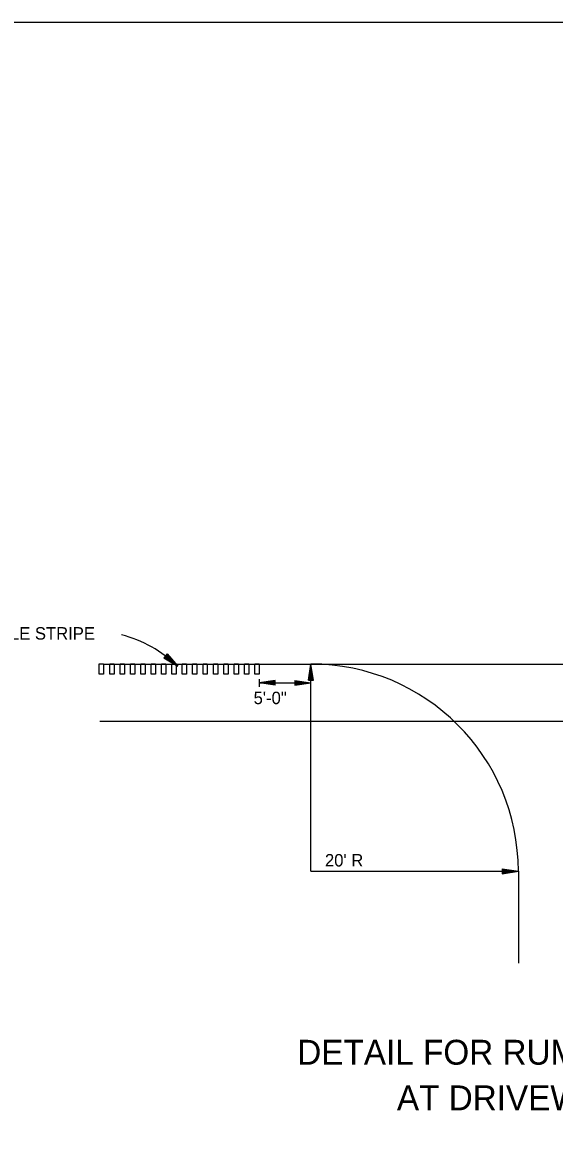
# Model space of a CAD drawing. Extents: x 1371343 to 1373043, y 378740 to 382040.
# Drawn here: x 1372437 to 1372692, y 380374 to 380915 of the extents above; entities that cross this region are included whole.
import ezdxf

# ---------------------------------------------------------------- set-up
doc = ezdxf.new("R2010")
doc.units = 0
for name, color, linetype in [('E_Existing ROW', 7, 'Continuous'), ('R_Border Notes', 7, 'Continuous'), ('R_Border PE', 7, 'Continuous')]:
    doc.layers.add(name, color=color, linetype=linetype)

msp = doc.modelspace()

# ---------------------------------------------------------------- linework, layer by layer
at = {"layer": 'E_Existing ROW'}
msp.add_lwpolyline([(1371367.92, 379865.49), (1373017.92, 379865.49), (1373017.92, 380915.49), (1371367.92, 380915.49)], close=True, dxfattribs=at)
at = {"layer": 'R_Border Notes'}
for p, q in [((1372475.93, 380607.52), (1372986.72, 380607.52)), ((1372575.6, 380508.02), (1372575.6, 380607.52)), ((1372550.73, 380600.19), (1372550.73, 380596.51)), ((1372550.73, 380598.48), (1372575.6, 380598.48)), ((1372474.28, 380580.11), (1372985.07, 380580.11)), ((1372575.6, 380508.02), (1372675.11, 380508.02)), ((1372675.11, 380508.02), (1372675.11, 380463.96))]:
    msp.add_line(p, q, dxfattribs=at)
for points in [[(1372474.03, 380602.59), (1372474.03, 380607.57), (1372476.11, 380607.57), (1372476.11, 380602.59), (1372474.03, 380602.59)], [(1372479.01, 380602.59), (1372479.01, 380607.57), (1372481.08, 380607.57), (1372481.08, 380602.59), (1372479.01, 380602.59)], [(1372483.98, 380602.59), (1372483.98, 380607.57), (1372486.06, 380607.57), (1372486.06, 380602.59), (1372483.98, 380602.59)], [(1372488.96, 380602.59), (1372488.96, 380607.57), (1372491.03, 380607.57), (1372491.03, 380602.59), (1372488.96, 380602.59)], [(1372493.93, 380602.59), (1372493.93, 380607.57), (1372496, 380607.57), (1372496, 380602.59), (1372493.93, 380602.59)], [(1372498.91, 380602.59), (1372498.91, 380607.57), (1372500.98, 380607.57), (1372500.98, 380602.59), (1372498.91, 380602.59)], [(1372503.88, 380602.59), (1372503.88, 380607.57), (1372505.95, 380607.57), (1372505.95, 380602.59), (1372503.88, 380602.59)], [(1372508.86, 380602.59), (1372508.86, 380607.57), (1372510.93, 380607.57), (1372510.93, 380602.59), (1372508.86, 380602.59)], [(1372513.83, 380602.59), (1372513.83, 380607.57), (1372515.9, 380607.57), (1372515.9, 380602.59), (1372513.83, 380602.59)], [(1372518.81, 380602.59), (1372518.81, 380607.57), (1372520.88, 380607.57), (1372520.88, 380602.59), (1372518.81, 380602.59)], [(1372523.78, 380602.59), (1372523.78, 380607.57), (1372525.85, 380607.57), (1372525.85, 380602.59), (1372523.78, 380602.59)], [(1372528.75, 380602.59), (1372528.75, 380607.57), (1372530.83, 380607.57), (1372530.83, 380602.59), (1372528.75, 380602.59)], [(1372533.73, 380602.59), (1372533.73, 380607.57), (1372535.8, 380607.57), (1372535.8, 380602.59), (1372533.73, 380602.59)], [(1372538.7, 380602.59), (1372538.7, 380607.57), (1372540.78, 380607.57), (1372540.78, 380602.59), (1372538.7, 380602.59)], [(1372543.68, 380602.59), (1372543.68, 380607.57), (1372545.75, 380607.57), (1372545.75, 380602.59), (1372543.68, 380602.59)], [(1372548.65, 380602.59), (1372548.65, 380607.57), (1372550.73, 380607.57), (1372550.73, 380602.59), (1372548.65, 380602.59)]]:
    msp.add_lwpolyline(points, dxfattribs=at)
for centre, radius, start, end in [((1372468.86, 380561.43), 62.18, 46.4613, 75.2786), ((1372575.6, 380508.02), 99.51, 0, 90)]:
    msp.add_arc(centre, radius, start, end, dxfattribs=at)
at = {"layer": 'R_Border PE'}
for p, q in [((1372506.53, 380612.35), (1372505.05, 380610.58)), ((1372505.05, 380610.58), (1372511.69, 380606.51)), ((1372505.17, 380610.73), (1372510.71, 380607.34)), ((1372505.3, 380610.88), (1372509.69, 380608.19)), ((1372505.42, 380611.03), (1372508.71, 380609.01)), ((1372505.55, 380611.18), (1372507.71, 380609.85)), ((1372505.67, 380611.33), (1372506.72, 380610.68)), ((1372505.91, 380611.6), (1372506.72, 380610.68)), ((1372506.03, 380611.75), (1372507.71, 380609.85)), ((1372506.16, 380611.91), (1372508.71, 380609.01)), ((1372506.28, 380612.05), (1372509.69, 380608.19)), ((1372506.41, 380612.2), (1372510.71, 380607.34)), ((1372506.53, 380612.35), (1372511.69, 380606.51)), ((1372574.44, 380599.82), (1372575.6, 380607.52)), ((1372574.44, 380599.82), (1372575.6, 380607.52)), ((1372574.64, 380599.82), (1372575.6, 380606.24)), ((1372574.64, 380599.82), (1372575.6, 380606.24)), ((1372574.83, 380599.82), (1372575.6, 380604.91)), ((1372574.83, 380599.82), (1372575.6, 380604.91)), ((1372575.03, 380599.82), (1372575.6, 380603.63)), ((1372575.03, 380599.82), (1372575.6, 380603.63)), ((1372576.76, 380599.82), (1372575.6, 380607.52)), ((1372576.76, 380599.82), (1372575.6, 380607.52)), ((1372576.56, 380599.82), (1372575.6, 380606.24)), ((1372576.56, 380599.82), (1372575.6, 380606.24)), ((1372576.37, 380599.82), (1372575.6, 380604.91)), ((1372576.37, 380599.82), (1372575.6, 380604.91)), ((1372576.17, 380599.82), (1372575.6, 380603.63)), ((1372576.17, 380599.82), (1372575.6, 380603.63)), ((1372558.43, 380599.64), (1372550.73, 380598.48)), ((1372558.43, 380597.33), (1372550.73, 380598.48)), ((1372558.43, 380599.45), (1372552.01, 380598.48)), ((1372558.43, 380597.52), (1372552.01, 380598.48)), ((1372558.43, 380599.25), (1372553.34, 380598.48)), ((1372558.43, 380597.72), (1372553.34, 380598.48)), ((1372558.43, 380599.06), (1372554.62, 380598.48)), ((1372558.43, 380597.91), (1372554.62, 380598.48)), ((1372558.43, 380598.86), (1372555.93, 380598.48)), ((1372558.43, 380598.11), (1372555.93, 380598.48)), ((1372558.43, 380598.66), (1372557.21, 380598.48)), ((1372558.43, 380598.3), (1372557.21, 380598.48)), ((1372558.43, 380597.33), (1372558.43, 380599.64)), ((1372567.89, 380599.64), (1372575.6, 380598.48)), ((1372567.89, 380599.64), (1372567.89, 380597.33)), ((1372567.89, 380599.45), (1372574.31, 380598.48)), ((1372567.89, 380599.25), (1372572.99, 380598.48)), ((1372567.89, 380599.06), (1372571.7, 380598.48)), ((1372567.89, 380598.86), (1372570.4, 380598.48)), ((1372567.89, 380598.66), (1372569.11, 380598.48)), ((1372567.89, 380597.33), (1372575.6, 380598.48)), ((1372567.89, 380598.11), (1372570.4, 380598.48)), ((1372567.89, 380597.72), (1372572.99, 380598.48)), ((1372567.89, 380597.52), (1372574.31, 380598.48)), ((1372567.89, 380597.91), (1372571.7, 380598.48)), ((1372567.89, 380598.3), (1372569.11, 380598.48)), ((1372574.44, 380599.82), (1372576.76, 380599.82)), ((1372574.44, 380599.82), (1372576.76, 380599.82)), ((1372575.23, 380599.82), (1372575.6, 380602.32)), ((1372575.23, 380599.82), (1372575.6, 380602.32)), ((1372575.42, 380599.82), (1372575.6, 380601.04)), ((1372575.42, 380599.82), (1372575.6, 380601.04)), ((1372575.98, 380599.82), (1372575.6, 380602.32)), ((1372575.98, 380599.82), (1372575.6, 380602.32)), ((1372575.78, 380599.82), (1372575.6, 380601.04)), ((1372575.78, 380599.82), (1372575.6, 380601.04)), ((1372667.4, 380509.17), (1372675.11, 380508.02)), ((1372667.4, 380509.17), (1372667.4, 380506.86)), ((1372667.4, 380509.17), (1372675.11, 380508.02)), ((1372667.4, 380509.17), (1372667.4, 380506.86)), ((1372667.4, 380508.98), (1372673.82, 380508.02)), ((1372667.4, 380508.98), (1372673.82, 380508.02)), ((1372667.4, 380508.78), (1372672.49, 380508.02)), ((1372667.4, 380508.78), (1372672.49, 380508.02)), ((1372667.4, 380508.59), (1372671.21, 380508.02)), ((1372667.4, 380508.59), (1372671.21, 380508.02)), ((1372667.4, 380508.39), (1372669.91, 380508.02)), ((1372667.4, 380508.39), (1372669.91, 380508.02)), ((1372667.4, 380508.2), (1372668.62, 380508.02)), ((1372667.4, 380508.2), (1372668.62, 380508.02)), ((1372667.4, 380506.86), (1372675.11, 380508.02)), ((1372667.4, 380507.64), (1372669.91, 380508.02)), ((1372667.4, 380507.25), (1372672.49, 380508.02)), ((1372667.4, 380507.05), (1372673.82, 380508.02)), ((1372667.4, 380507.44), (1372671.21, 380508.02)), ((1372667.4, 380507.84), (1372668.62, 380508.02)), ((1372667.4, 380506.86), (1372675.11, 380508.02)), ((1372667.4, 380507.64), (1372669.91, 380508.02)), ((1372667.4, 380507.25), (1372672.49, 380508.02)), ((1372667.4, 380507.05), (1372673.82, 380508.02)), ((1372667.4, 380507.44), (1372671.21, 380508.02)), ((1372667.4, 380507.84), (1372668.62, 380508.02))]:
    msp.add_line(p, q, dxfattribs=at)

# ---------------------------------------------------------------- texts
at = {"layer": 'R_Border Notes'}
for s, height, p in [('RUMBLE STRIPE', 5.9696, (1372407.62, 380619.27)), ('5\'-0"', 5.97, (1372548.06, 380588.28)), ("20' R", 5.97, (1372582.3, 380510.34)), ('DETAIL FOR RUMBLE STRIPE GAP', 11.9393, (1372569.02, 380415.18)), ('AT DRIVEWAY TURNOUTS', 11.9393, (1372616.83, 380393.29))]:
    msp.add_text(s, height=height, dxfattribs=at).set_placement(p)

doc.saveas('drawing.dxf')
